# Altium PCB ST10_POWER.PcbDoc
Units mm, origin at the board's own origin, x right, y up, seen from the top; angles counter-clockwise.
Board outline 37 x 13.7 mm, 2 copper layers (Top Layer, Bottom Layer), stack 1.576 mm thick; 16 components, 6 nets, 41 pads, 27 vias.
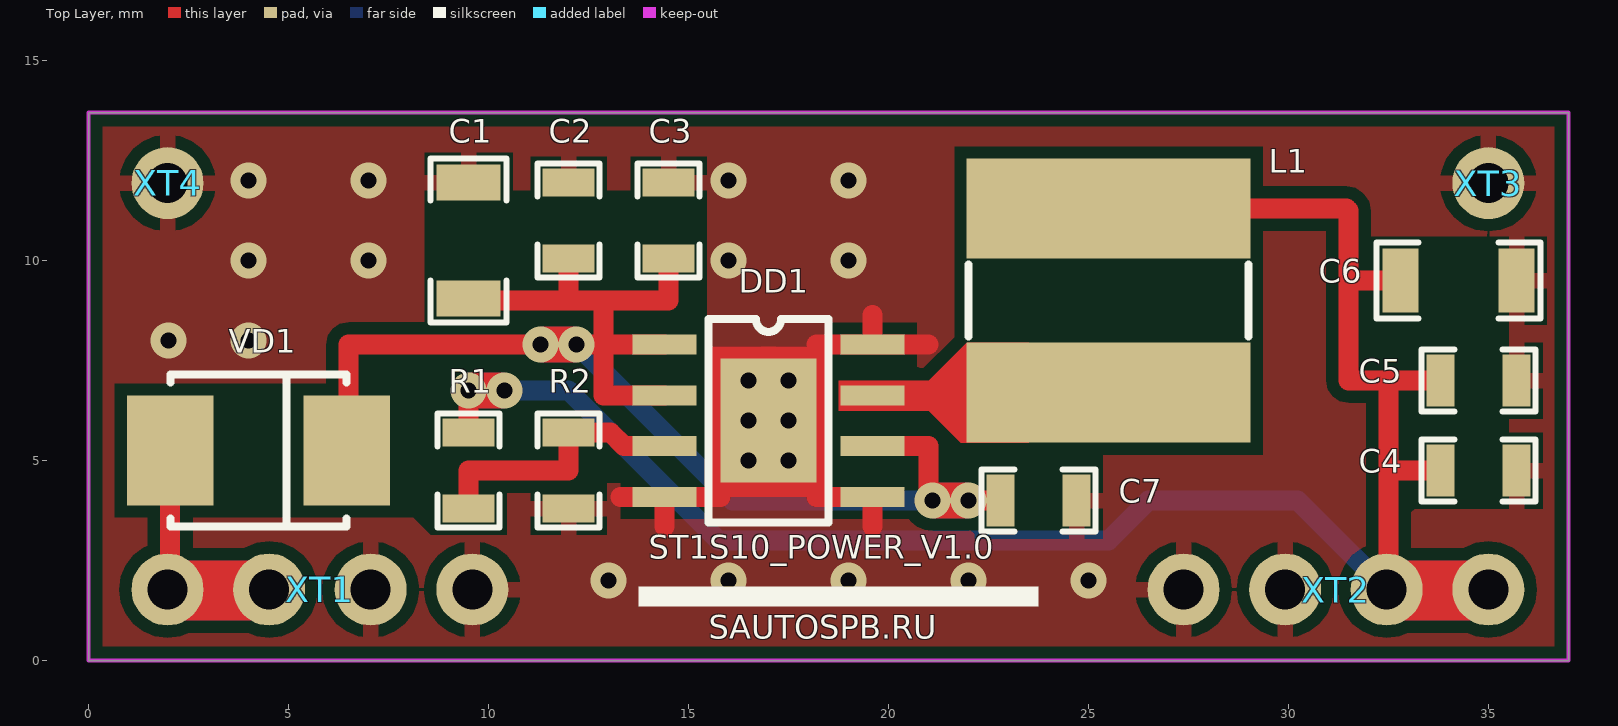
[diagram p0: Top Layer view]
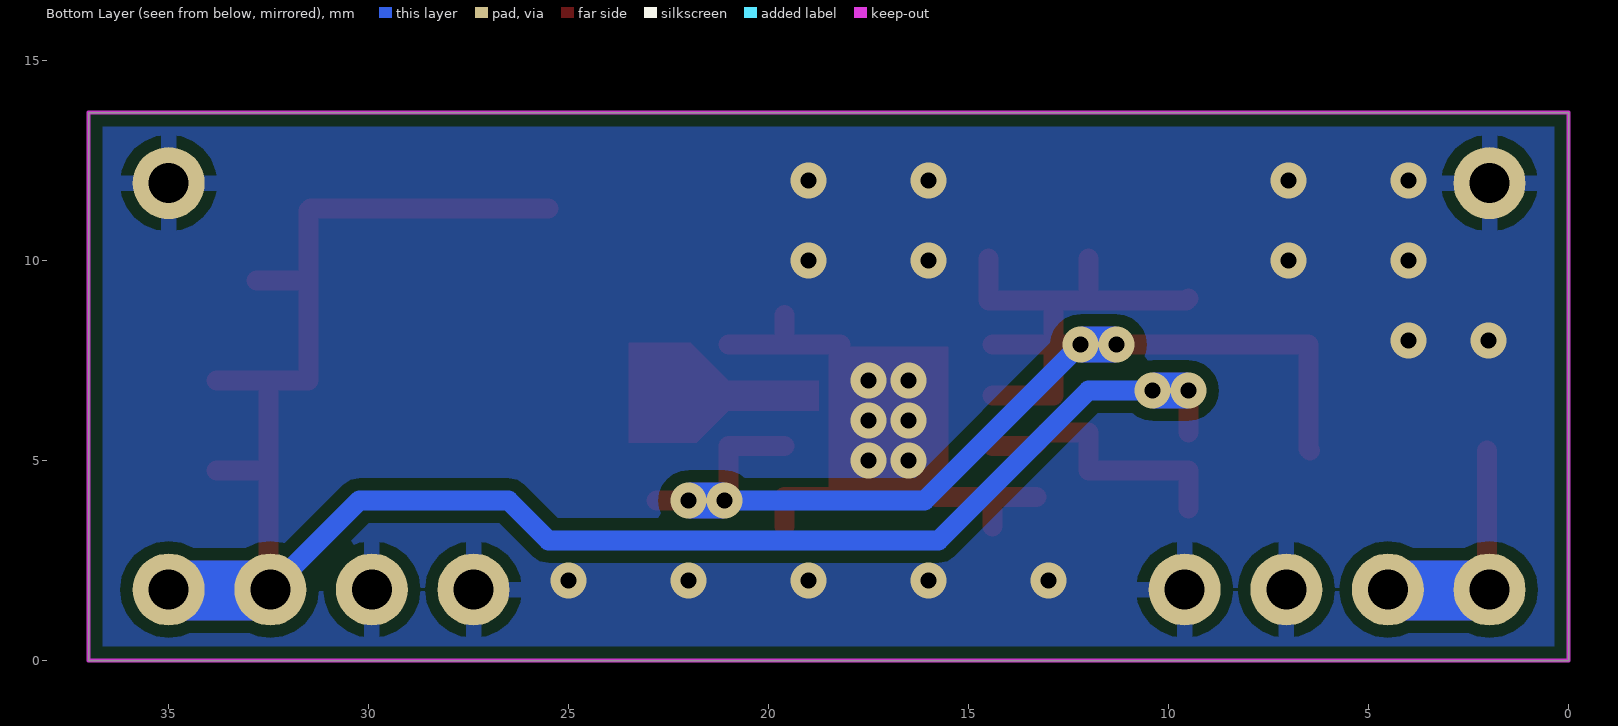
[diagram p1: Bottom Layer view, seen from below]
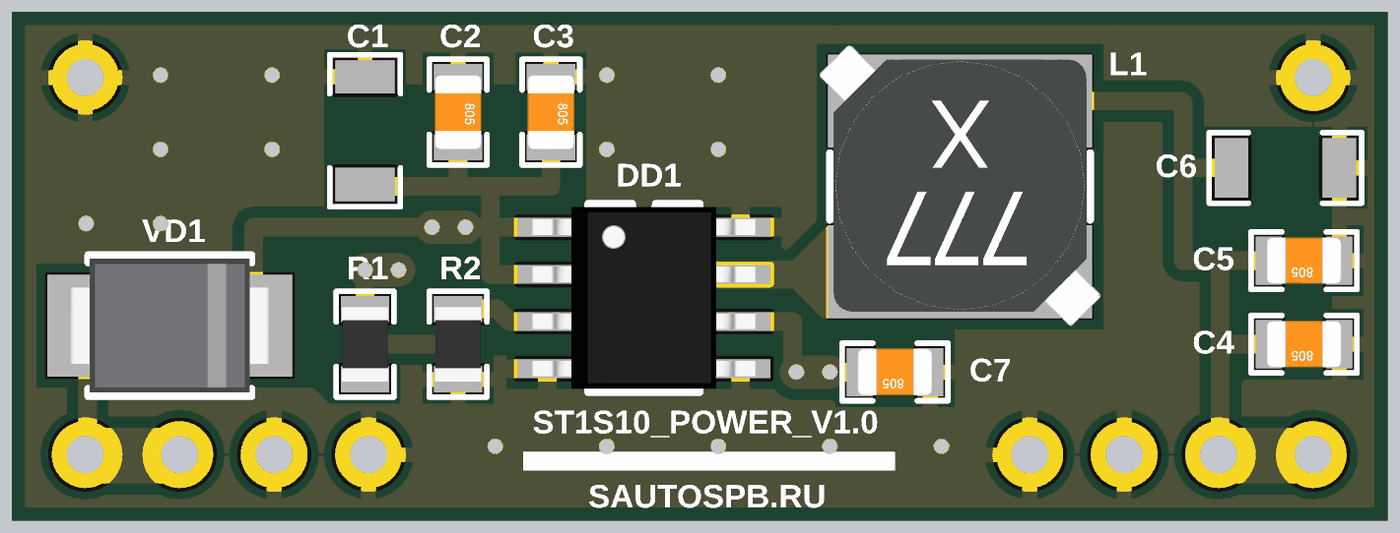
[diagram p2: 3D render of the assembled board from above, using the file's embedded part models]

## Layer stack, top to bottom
Top Solder: solder mask 0.012, Solder Resist, Dk 3.5
Top Layer: signal copper 0.018
Dielectric 1: dielectric 1.54, FR-4, Dk 4.8
Bottom Layer: signal copper 0.018
Bottom Solder: solder mask 0.012, Solder Resist, Dk 3.5

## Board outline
0,0 37,0 37,13.7 0,13.7

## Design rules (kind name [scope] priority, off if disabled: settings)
Clearance Clearance_Poly_Inner_Keepout [InPolygon AND OnMid vs (IsTrack AND OnLayer('Keep-Out Layer')) OR HoleSize] p1: gap=0.5
Clearance Clearance_Poly_Inner [InPolygon AND OnMid] p2: gap=0.3
Clearance Clearance_Poly [InPolygon] p3: gap=0.3
Clearance [All] p4: gap=0.2
ComponentClearance [All] p1: gap=0 collisioncheckmode=3 verticalgap=0 showdistances=FALSE
Height [All] p1: minheight=0 maxheight=100 prefheight=20
HoleSize [All] p1: absolutevalues=TRUE maxlimit=10 minlimit=0.3 maxpercent=80.000 minpercent=20.000
HoleToHoleClearance [All] p1: gap=0.3 allowstackedmicrovias=TRUE
MinimumSolderMaskSliver [All] p1: minsoldermaskwidth=0
PlaneClearance [All] p1: clearance=0.5
PlaneConnect [All] p1: planeconnectstyle=Relief reliefexpansion=0.508 reliefentries=4 reliefconductorwidth=0.4 reliefairgap=0.254
PolygonConnect PolygonConnect_Via [IsVia vs IsPolygon] p1: connectstyle=Direct reliefconductorwidth=0.254 reliefentries=4 polygonreliefangle="90 Angle" airgapwidth=0.254
PolygonConnect [All] p2: connectstyle=Relief reliefconductorwidth=0.4 reliefentries=4 polygonreliefangle="90 Angle" airgapwidth=0.3
RoutingVias [All] p1: holewidth=0.4 width=0.9 viastyle="Through Hole" minholewidth=0.3 minwidth=0.7 maxholewidth=3 maxwidth=5
SilkToSilkClearance [All] p1: silktosilkclearance=0.02
SilkToSolderMaskClearance SilkscreenOverComponentPads [IsPad] p1: minsilkscreentomaskgap=0.02 clearancetoexposedcopper=TRUE
SolderMaskExpansion [All] p1: expansion=0.05
Width [All] p1: maxlimit=10 minlimit=0.2 preferedwidth=0.5
21 further rules are at their usual default settings.

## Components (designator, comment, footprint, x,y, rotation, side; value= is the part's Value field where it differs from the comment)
DD1 "ST1S10" SO-8EPAD 17,6 r0 top
L1 "3.3uH" MSS7341 25.5,9 r180 top
R1 "120K" RES_0805 9.5,4.75 r90 top
R2 "22K" RES_0805 12,4.75 r90 top
VD1 "SS24" SMB 4.25,5.25 r0 top
XT1 "*" PLS-4_1 5.785,1.775 r0 top
XT2 "*" PLS-4_1 31.185,1.775 r180 top
XT3 "*" PLS-1_1 34.995,11.935 r0 top
XT4 "*" PLS-1_1 1.975,11.935 r0 top
С1 "10uF" CAP_CER_1206 9.5,10.5 r270 top
С2 "10uF" CAP_CER_0805 12,11 r270 top
С3 "10uF" CAP_CER_0805 14.5,11 r270 top
С4 "10uF" CAP_CER_0805 34.75,4.75 r180 top
С5 "10uF" CAP_CER_0805 34.75,7 r180 top
С6 "10uF" CAP_CER_1206 34.25,9.5 r180 top
С7 "0.1uF" CAP_CER_0805 23.75,4 r180 top

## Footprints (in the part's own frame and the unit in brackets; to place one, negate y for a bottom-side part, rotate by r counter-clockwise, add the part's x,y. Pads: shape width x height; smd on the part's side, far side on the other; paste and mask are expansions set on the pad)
CAP_CER_0805 [mm]
  rect 0.7x1.3 smd mask+0.1: 1(-0.95,0) 2(0.95,0)
  silkscreen extent -1.43,-0.78 1.43,0.78, body extent -1,-0.62 1,0.63, height 0.78
CAP_CER_1206 [mm]
  rect 0.9x1.6 smd mask+0.1: 1(-1.45,0) 2(1.45,0)
  silkscreen extent -2.05,-0.95 2.05,0.95, body extent -1.6,-0.8 1.6,0.8, height 1
MSS7341 [mm] "Shielded Inductor, 7.1x7.1mm"
  rect 7.1x2.5 smd mask+0.05: 1(0,-2.3) 2(0,2.3)
  silkscreen extent -3.5,-0.9 3.5,0.9, body extent -3.78,-3.8 3.78,3.76, height 4.1
PLS-1_1 [mm] "PLS-1 Connector 2.54mm pitch"
  round 1.8 hole 1 paste+0 mask+0.1: 1(0,0)
PLS-4_1 [mm] "PLS-4 Connector 2.54mm pitch"
  round 1.8 hole 1 paste+0 mask+0.1: 1(-3.81,0) 3(1.27,0) 4(3.81,0)
  round 1.8 hole 1 mask+0.1: 2(-1.27,0)
RES_0805 [mm]
  rect 0.7x1.3 smd mask+0.1: 1(-0.95,0) 2(0.95,0)
  silkscreen extent -1.43,-0.78 1.43,0.78, body extent -1,-0.62 1,0.63, height 0.5
SMB [mm] "SMB Case Diode/Supressor"
  rect 2.159x2.743 smd mask+0.075: 1(-2.21,0) 2(2.21,0)
  silkscreen extent -2.2,-1.9 2.2,1.9, body extent -2.7,-1.8 2.7,1.8, height 2.3
SO-8EPAD [mm] "Small Outline Integrated Circuit, 9 Pins"
  rect 2.41x3.1 smd mask+0.05: 0(0,0)
  rect 1.6x0.5 smd mask+0.1: 1(-2.6,1.9) 2(-2.6,0.63) 3(-2.6,-0.64) 4(-2.6,-1.91) 5(2.6,-1.91) 6(2.6,-0.64) 7(2.6,0.63) 8(2.6,1.9)
  silkscreen extent -1.5,-2.55 1.5,2.53, body extent -3,-2.45 2.99,2.45, height 1.6

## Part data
DD1: "Step-Down3 A, 900 kHz, monolithic synchronous step-down regulator IC"
L1: library part L, "Inductor"
R1 R2: library part RES_SMD, "Chip Resistor"
VD1: library part "Diode Shottky", "Diode"
XT1 XT2: library part PLS-4, "Header Connector"
XT3 XT4: library part PLS-1, "Header Connector"
С1 С2 С3 С4 С5 С6 С7: library part CAP_CER, "Fixed Ceramic Capacitor"

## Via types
v1: diameter 0.9, hole 0.4, Top Layer to Bottom Layer, tented both sides, 27 vias

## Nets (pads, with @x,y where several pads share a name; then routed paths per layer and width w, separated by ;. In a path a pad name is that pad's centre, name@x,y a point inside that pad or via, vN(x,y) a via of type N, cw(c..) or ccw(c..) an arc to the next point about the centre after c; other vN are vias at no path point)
GND: DD1.0 DD1.4 DD1.5 DD1.8 R2.1 XT1.3 XT1.4 XT2.3 XT2.4 XT3.1 XT4.1 С1.1 С2.1 С3.1 С4.1 С5.1 С6.1 С7.1 | length 8.9
  Top Layer w0.5: 13.3,4.09 DD1.4 ; 14.4,3.35 DD1.4 ; 15.8,4.09 DD1.4 ; 18.2,4.09 DD1.5 19.6,3.35 ; 18.2,7.9 DD1.8 ; 19.6,8.64 DD1.8 ; 21,7.9 DD1.8
  other v1: 13,2 16,2 19,2 22,2 25,2 16.5,5 17.5,5 16.5,6 17.5,6 16.5,7 17.5,7 2,8 4,8 4,10 7,10 16,10 19,10 4,12 7,12 16,12 19,12
NetDD1_3: DD1.3 R1.1 R2.2 | length 6.9
  Top Layer w0.5: R1.1 9.5,4.75 12,4.75 R2.2 13.05,5.7 13.39,5.36 DD1.3
NetDD1_7: DD1.7 L1.2
NetVD1_1: VD1.1 XT1.1 XT1.2 | length 3.5
  Top Layer w0.5: XT1.1 2.04,1.84 VD1.1
VIN: DD1.1 DD1.2 DD1.6 VD1.2 С1.2 С2.2 С3.2 С7.2 | length 36.5
  Top Layer w0.5: VD1.2 6.5,5.29 6.5,7.9 v1(11.3,7.9) v1(12.2,7.9) 12.87,7.9 ; С1.2 9.55,9 12,9 ; С2.2 12,9 ; 13.09,7.9 DD1.1 ; DD1.2 12.87,6.63 12.87,7.9 ; С3.2 14.5,9 13,9 ; DD1.6 21,5.36 21,4 v1(21.1,4) v1(22,4) С7.2 ; 12,9 13,9 ; 12.87,7.9 12.87,8.87 13,9
  Bottom Layer w0.5: v1(12.2,7.9) 16.1,4 v1(21.1,4)
VOUT: L1.1 R1.2 XT2.1 XT2.2 С4.2 С5.2 С6.2 | length 47.3
  Top Layer w0.5: R1.2 v1(9.5,6.75) v1(10.4,6.75) ; L1.1 31.45,11.3 31.5,11.25 31.5,9.5 ; XT2.2 32.5,1.82 32.5,4.75 ; С6.2 31.5,9.5 ; С4.2 32.5,4.75 ; С5.2 32.5,7 ; 31.5,9.5 31.5,7 32.5,7 ; 32.5,4.75 32.5,7
  Bottom Layer w0.5: v1(10.4,6.75) 12,6.75 15.75,3 25.5,3 26.5,4 30.23,4 XT2.2

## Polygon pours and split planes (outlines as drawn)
GND on Top Layer "Top Layer-No Net" (solid, remove dead copper, pour order 4): 0,0 37,0 37,13.7 0,13.7
GND on Bottom Layer "Top Layer-No Net" (solid, remove dead copper, pour order 6): 0,0 37,0 37,13.7 0,13.7

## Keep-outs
Keep-Out Layer:
  the board outline again, w0.1

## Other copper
Top Layer:
  rectangle net GND: 15.5,4.088 18.5,7.85
  region net VOUT: 10.4,7.2 9.5,7.2 9.5,6.3 10.4,6.3
  rectangle net VOUT: 32.455,1 34.995,2.5
  rectangle net NetVD1_1: 1.975,1 4.515,2.5
  region net VIN: 22,4.45 21.1,4.45 21.1,3.55 22,3.55
  rectangle net VIN: 11.3,7.45 12.2,8.35
  pour cut-out: 35.5,7.95 35.5,8.4 33.6,8.4 33.15,7.95
  pour cut-out: 35.5,6.05 35.5,5.7 33.15,5.7 33.15,6.05
  pour cut-out: 25.35,4.95 25.35,5.15 24.75,5.75 24.5,5.5 24.5,4.95
  pour cut-out: 12.95,4.45 13.3,4.45 13.3,4.81 12.98,4.81 12.95,4.84
  pour cut-out: 8.55,3.15 8.122,3.579 7.839,3.579 7.839,5.05 8.55,5.05
  pour cut-out: 15.5,8.45 15.45,8.5 15.45,9.4 15.061,9.4 14.895,9.235 14.895,8.45
  pour cut-out: 12.95,9.561 13.55,9.561 13.55,11.75 12.95,11.75
  pour cut-out: 10.6,11.75 11.05,11.75 11.05,9.561 10.6,9.561
  pour cut-out: 24.5,4.95 24.5,5.5 23.75,5.5 23.75,4.95
  pour cut-out: 20.7,3.54 18.5,3.54 18.5,4.635 18.505,4.64 20.7,4.64
  pour cut-out: 20.7,4.81 18.5,4.81 18.5,5.905 18.505,5.91 20.7,5.91
  pour cut-out: 20.7,6.08 18.5,6.08 18.5,7.175 18.505,7.18 20.7,7.18
  pour cut-out: 20.7,7.35 18.5,7.35 18.5,8.445 18.505,8.45 20.7,8.45
  pour cut-out: 13.3,7.35 15.5,7.35 15.5,8.445 15.495,8.45 13.3,8.45
  pour cut-out: 13.3,6.08 15.5,6.08 15.5,7.175 15.495,7.18 13.3,7.18
  pour cut-out: 13.3,4.81 15.5,4.81 15.5,5.905 15.495,5.91 13.3,5.91
  pour cut-out: 13.3,3.54 15.5,3.54 15.5,4.808 13.3,4.813
  pour cut-out: 21.65,9.75 21.65,8.25 29.35,8.25 29.35,9.75
  pour cut-out: 33.55,8.4 34.95,8.4 34.95,10.6 33.55,10.6
  pour cut-out: 34.45,3.8 35.05,3.8 35.05,5.7 34.45,5.7
  pour cut-out: 34.45,6.05 35.05,6.05 35.05,7.95 34.45,7.95
  pour cut-out: 23.45,3.05 24.05,3.05 24.05,4.95 23.45,4.95
  pour cut-out: 11.05,5.05 11.05,4.45 12.95,4.45 12.95,5.05
  pour cut-out: 8.55,5.05 8.55,4.45 10.45,4.45 10.45,5.05
  pour cut-out: 13.55,11.3 13.55,10.7 15.45,10.7 15.45,11.3
  pour cut-out: 11.05,11.3 11.05,10.7 12.95,10.7 12.95,11.3
  pour cut-out: 8.4,11.2 8.4,9.8 10.6,9.8 10.6,11.2
  pour cut-out: 3.419,6.921 5.081,6.921 5.081,3.579 3.419,3.579
  region net NetDD1_7: 18.75,7 18.75,6.25 21,6.25 21.8,5.45 23.5,5.45 23.5,7.95 21.95,7.95 21,7
Bottom Layer:
  rectangle net VOUT: 9.5,6.3 10.4,7.2
  region net VOUT: 34.995,2.5 32.455,2.5 32.455,1 34.995,1
  region net NetVD1_1: 4.515,2.5 1.975,2.5 1.975,1 4.515,1
  region net VIN: 12.2,8.35 11.3,8.35 11.3,7.45 12.2,7.45
  region net VIN: 22,4.45 21.1,4.45 21.1,3.55 22,3.55

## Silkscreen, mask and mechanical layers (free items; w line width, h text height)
Top Overlay:
  region: 23.75,1.85 13.75,1.85 13.75,1.35 23.75,1.35
  text "ST1S10_POWER_V1.0" at 14,2.35 h1
  text "SAUTOSPB.RU" at 15.5,0.35 h1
